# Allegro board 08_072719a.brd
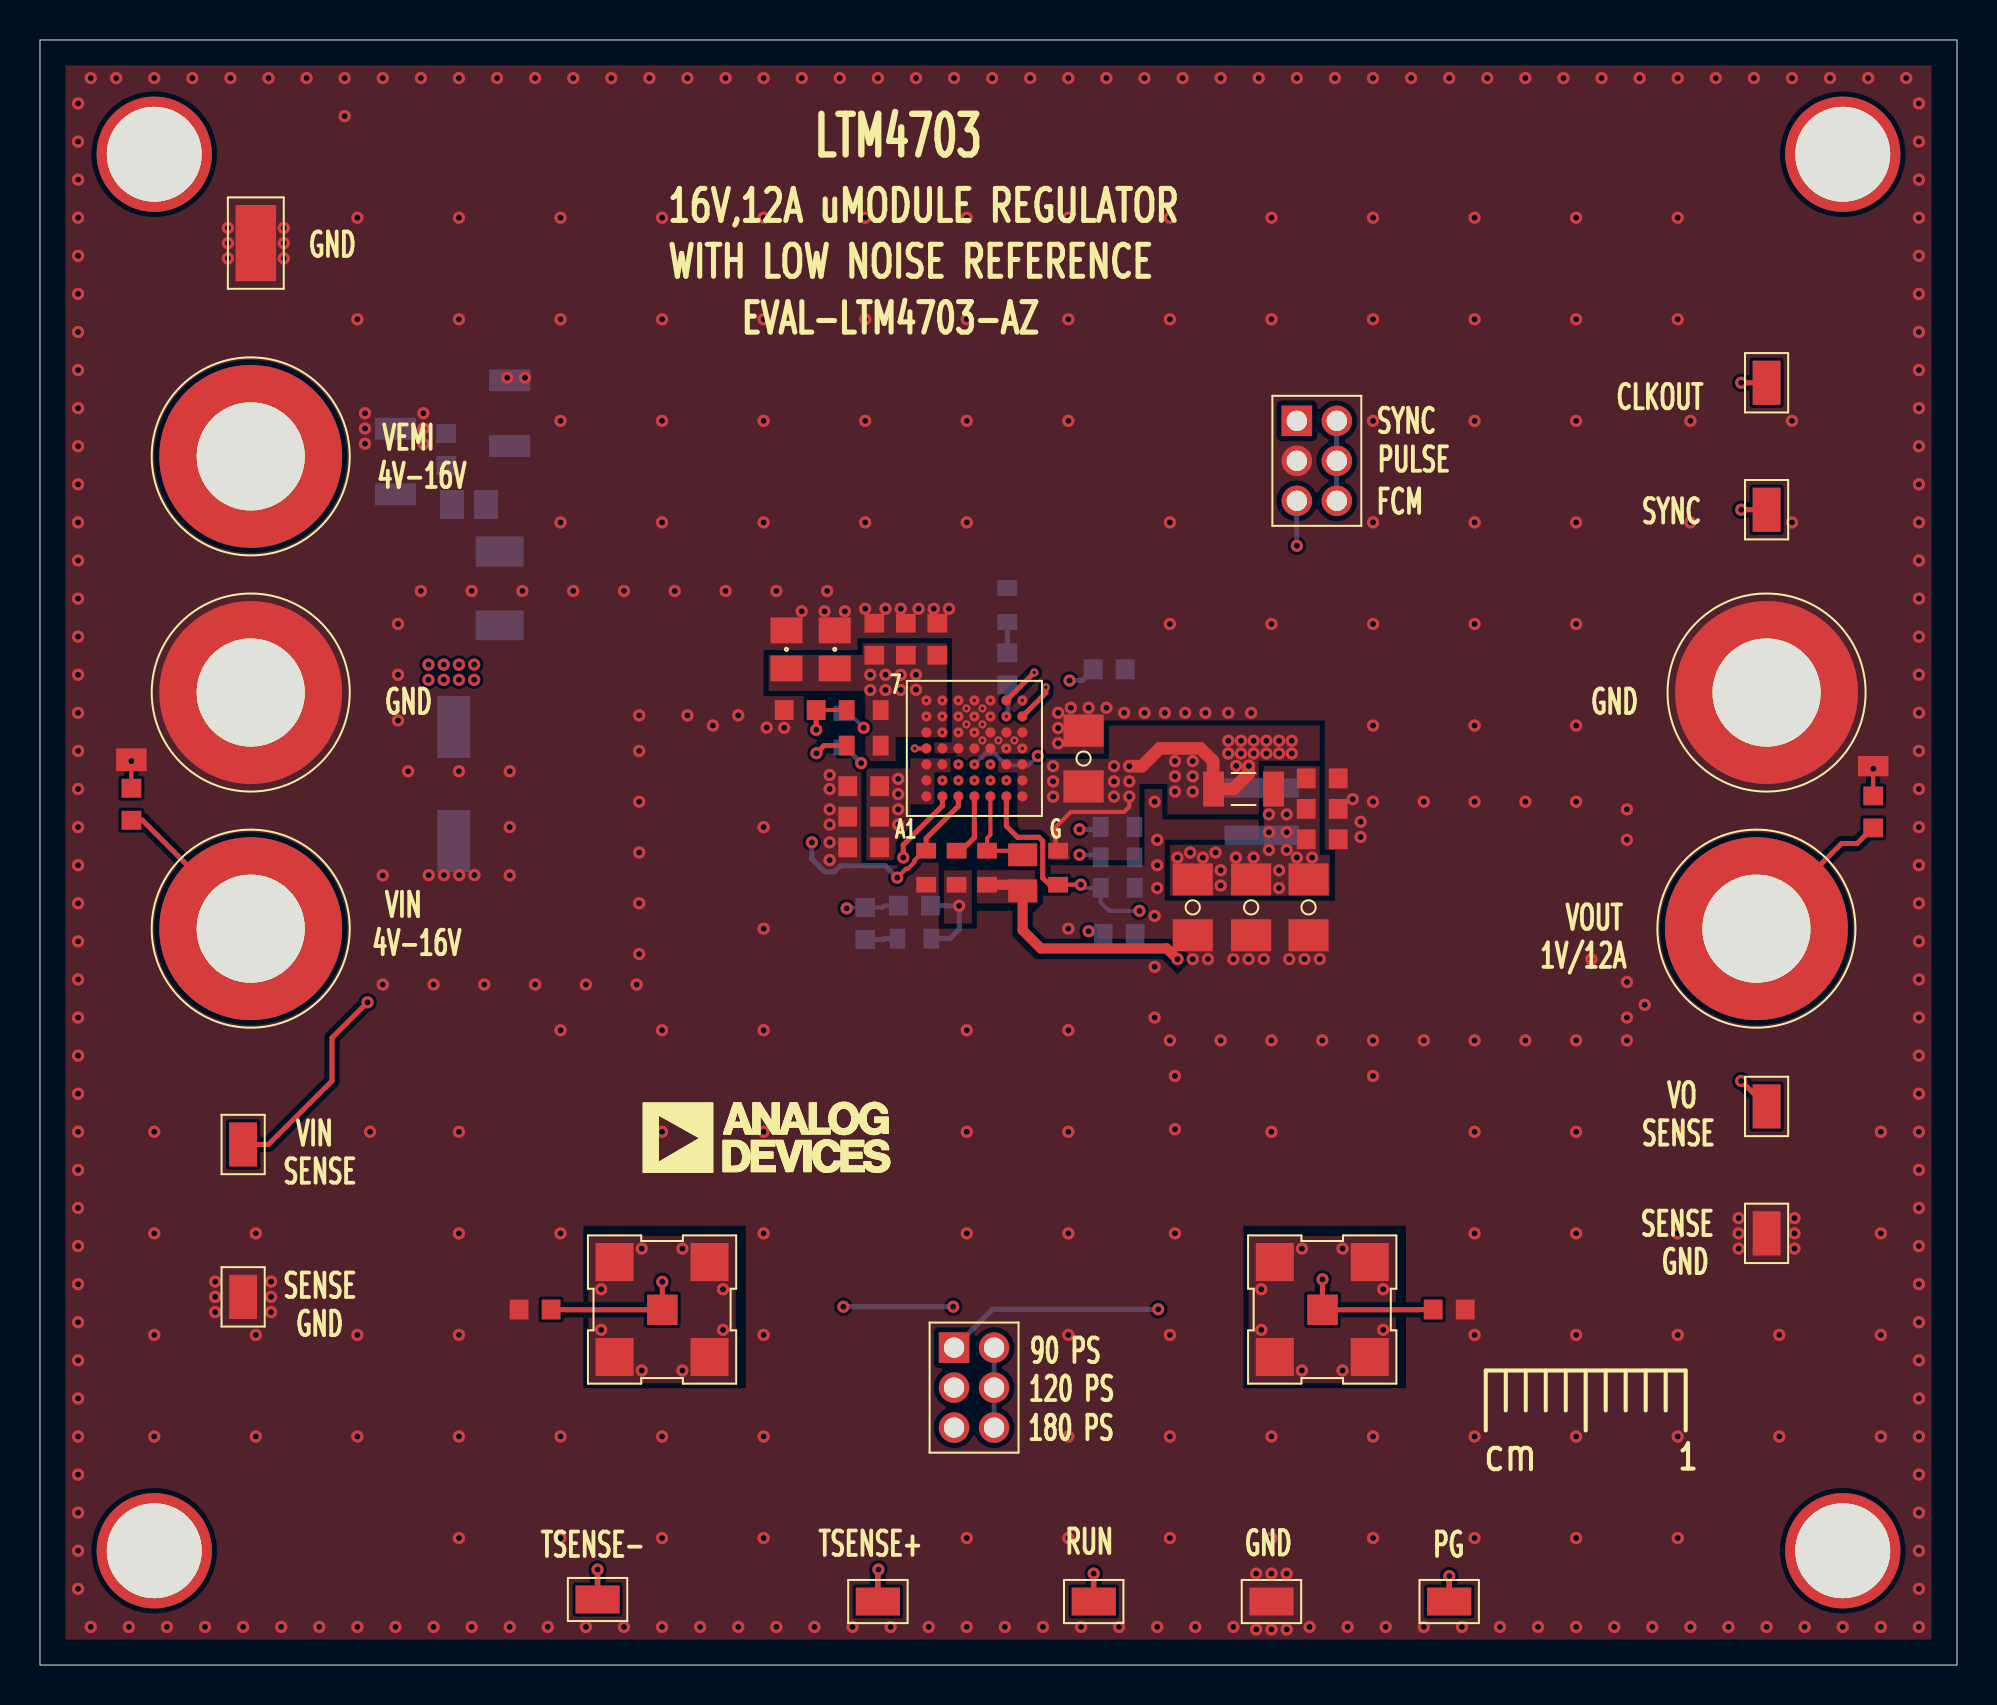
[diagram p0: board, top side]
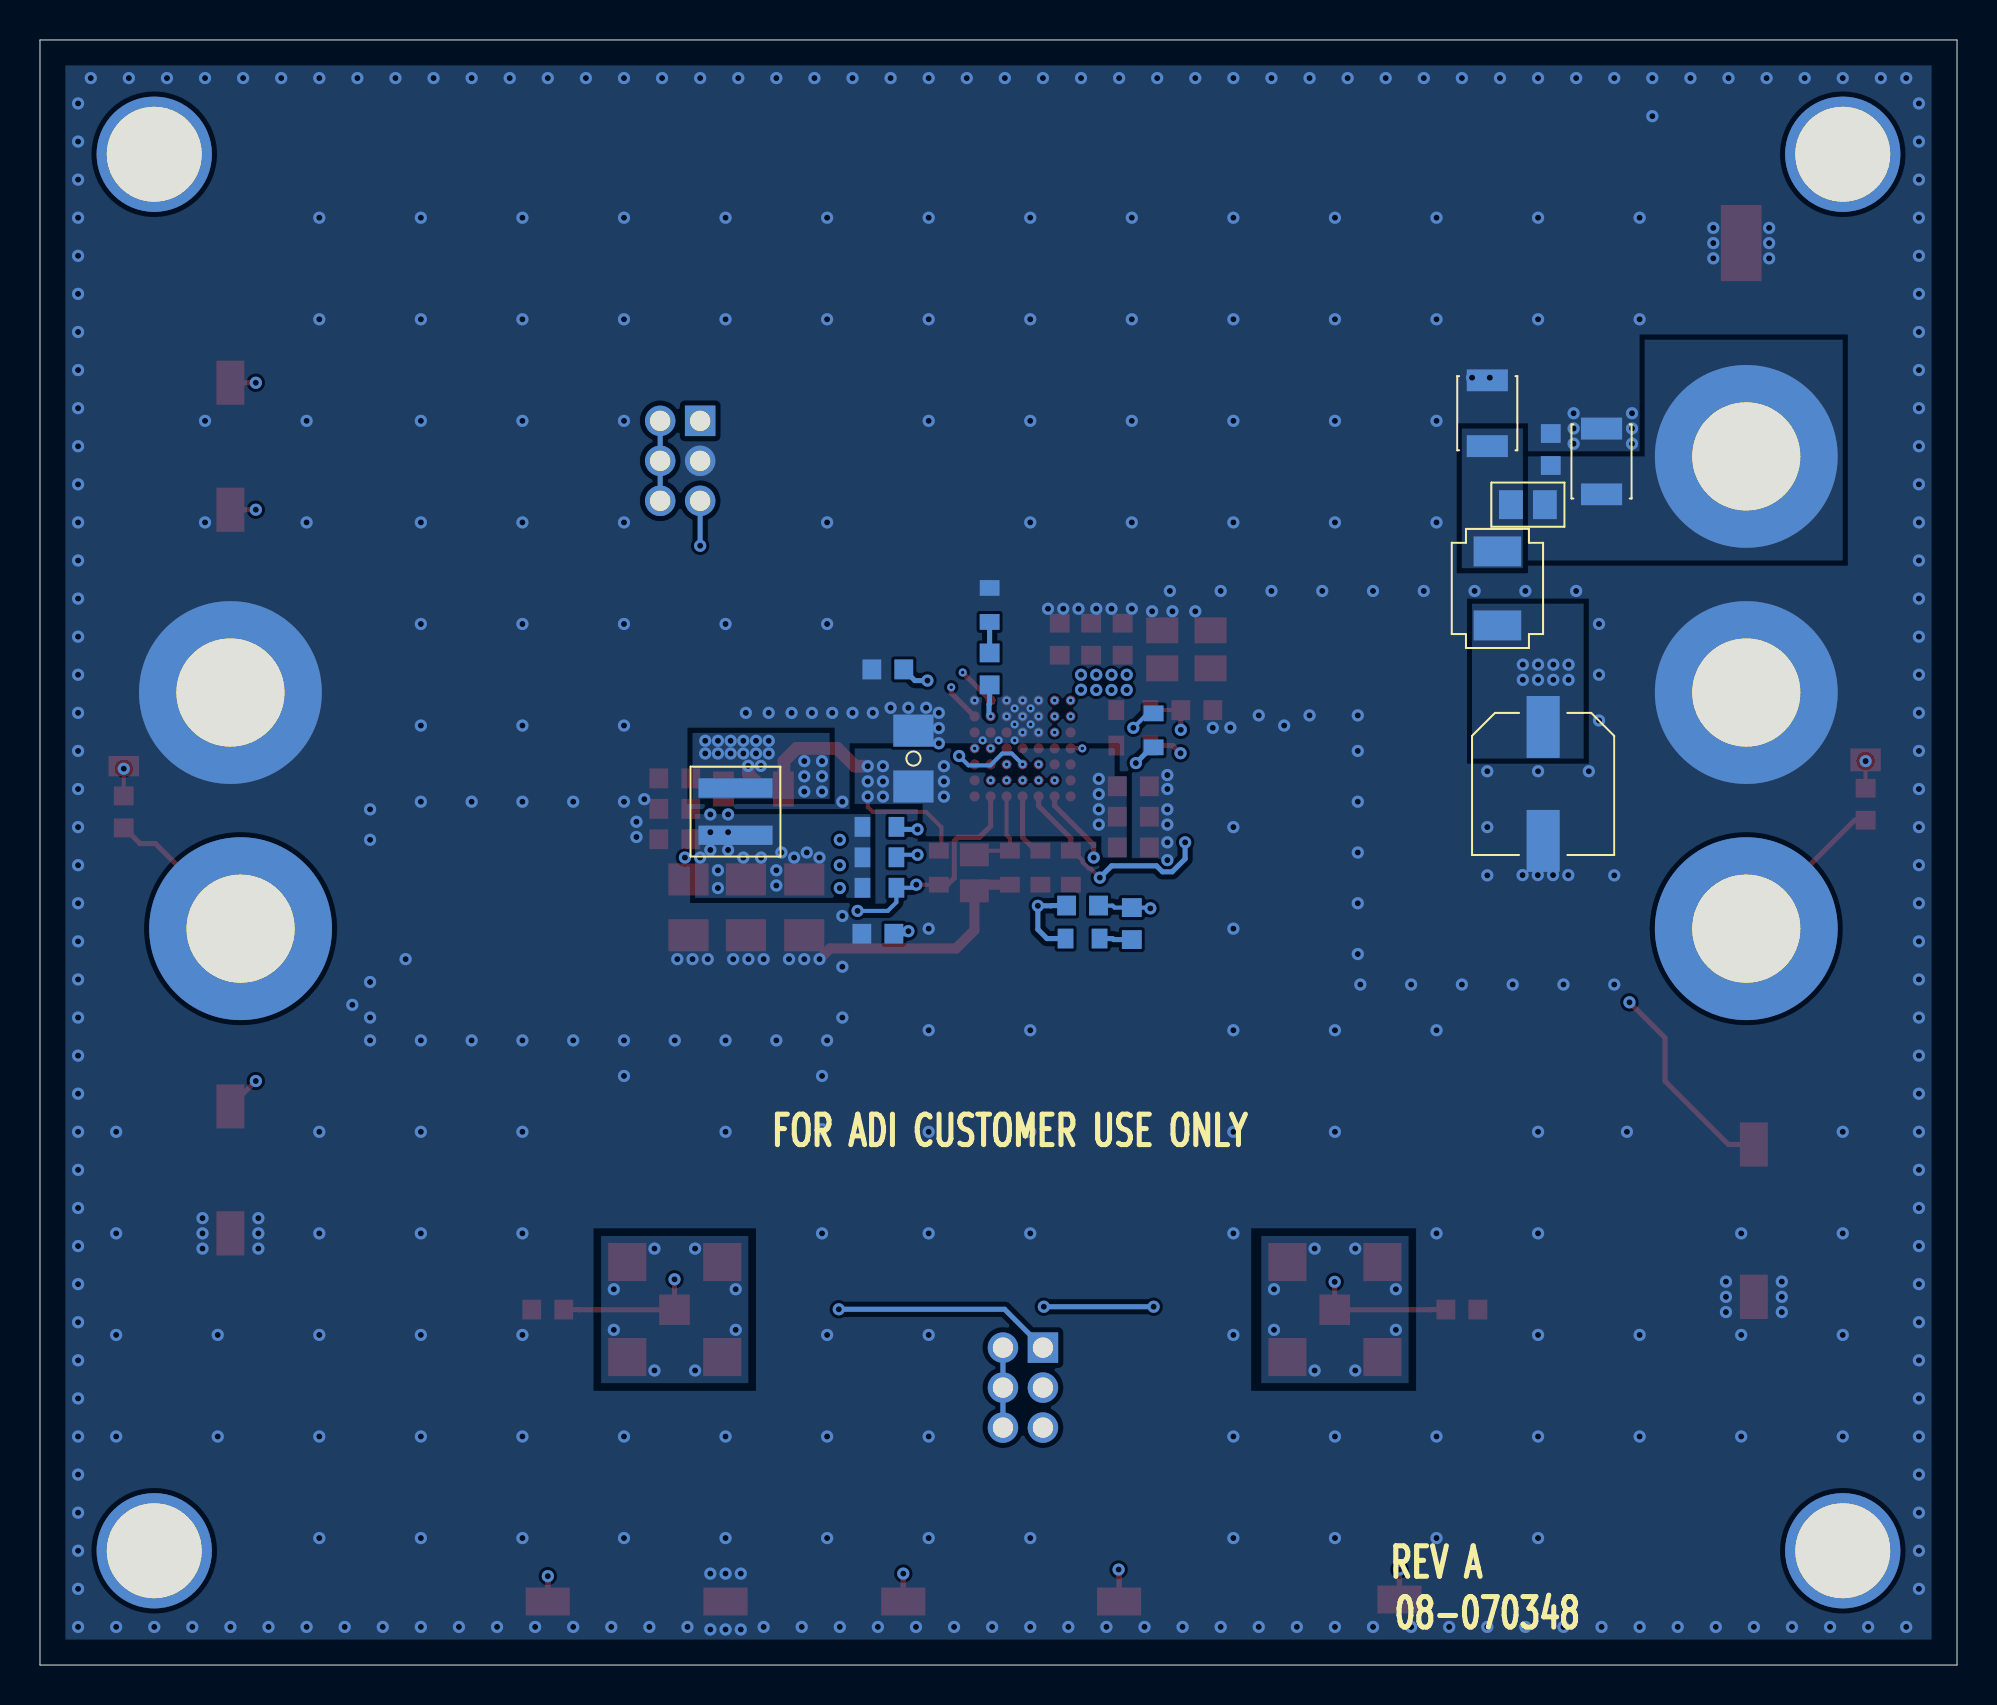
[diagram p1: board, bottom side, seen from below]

Outline 95.89 x 81.28 mm; copper layers: TOP, LAYER2, LAYER3, BOTTOM. Coordinates in mm from the lower left corner of the outline.
Outline path: 0,81.28 0,0 95.89,0 95.89,81.28 0,81.28

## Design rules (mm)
constraint set DEFAULT: min track width 0.203

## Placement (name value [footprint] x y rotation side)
C1  100uF  [CPLSMSQ260H315]  20.7 44.07 270 bottom
C2  22uF  [C0805H60]  39.75 50.8 270 top
C3  2.2uF  [C0603]  4.57 43.05 270 top
C4  2.2uF  [C0603]  43.31 51.31 270 top
C5  2.2uF  [C0603]  41.73 51.31 270 top
C6  100uF  [C1206H71]  52.2 45.34 270 top
C7  TBD0603  [C0603]  53.48 49.8 180 bottom
C8  TBD0603  [C0603]  48.39 49.82 270 bottom
C9  1UF  [C0805H55]  49.15 39.62 90 top
C10  1UF  [C0603]  20.32 60.79 270 bottom
C11  22uF  [C1210H106]  17.78 60.2 270 bottom
C12  22uF  [C1210H106]  23.5 62.61 270 bottom
C13  10uF  [C0603]  41.2 42.43 0 top
C14  10uF  [C0603]  41.2 43.95 0 top
C15  10uF  [C0603]  64.13 42.82 180 top
C16  10uF  [C0603]  91.69 42.67 270 top
C17  100uF  [C1206H71]  63.45 37.9 90 top
C18  0.1uF  [C0603]  38.02 47.76 0 top
C19  100uF  [C1206H71]  52.2 45.34 270 bottom
C20  TBD0603  [C0603]  43.74 37.99 180 bottom
C21  10uF  [C0603]  41.2 40.89 0 top
C22  100uF  [C1206H71]  60.58 37.9 90 top
C23  0.1uF  [C0603]  24.77 17.78 0 top
C24  0.1uF  [C0603]  70.48 17.78 180 top
C25  TBD0603  [C0603]  53.98 36.58 180 bottom
C26  22uF  [C0805H60]  37.34 50.8 270 top
C27  2.2uF  [C0603]  44.88 51.31 270 top
C33  100uF  [C1206H71]  57.66 37.9 90 top
C34  10uF  [C0603]  64.13 44.35 180 top
C35  10uF  [C0603]  64.13 41.3 180 top
C60  0.015UF  [C0603]  41.27 37.08 90 bottom
E1  575-4  [CNBANANAD312LD203]  10.54 36.83 90 top
E2  S2751-46R  [CNHARWINS2751-46R]  61.59 3.17 0 top
E3  575-4  [CNBANANAD312LD203]  85.85 36.83 90 top
E4  S2751-46R  [CNHARWINS2751-46R]  52.7 3.17 0 top
E5  5019  [CNKEY5019]  10.79 71.12 90 top
E6  S2751-46R  [CNHARWINS2751-46R]  10.16 26.03 90 top
E7  S2751-46R  [CNHARWINS2751-46R]  70.48 3.17 0 top
E8  575-4  [CNBANANAD312LD203]  86.36 48.64 90 top
E9  S2751-46R  [CNHARWINS2751-46R]  86.36 64.13 90 top
E10  575-4  [CNBANANAD312LD203]  10.54 48.64 90 top
E11  S2751-46R  [CNHARWINS2751-46R]  86.36 57.79 90 top
E12  S2751-46R  [CNHARWINS2751-46R]  10.16 18.41 90 top
E13  S2751-46R  [CNHARWINS2751-46R]  86.36 21.59 90 top
E14  S2751-46R  [CNHARWINS2751-46R]  41.91 3.17 0 top
E15  S2751-46R  [CNHARWINS2751-46R]  27.89 3.28 0 top
E16  S2751-46R  [CNHARWINS2751-46R]  86.36 27.94 90 top
E17  575-4  [CNBANANAD312LD203]  10.54 60.45 90 top
FB1  30OHM AT 100MEGHZ  [L0805H43]  21.46 58.04 0 bottom
J1  732511350  [CNMOLEX73251135X]  31.12 17.78 0 top
J2  732511350  [CNMOLEX73251135X]  64.13 17.78 0 top
JP1  TMM-103-02-L-D  [CNTHMHDR2X3L236W155H225]  62.87 62.23 270 top
JP2  TMM-103-02-L-D  [CNTHMHDR2X3L236W155H225]  45.72 15.88 270 top
L1  0.1UH  [LSMSQ160H79]  22.99 53.85 270 bottom
L2  0.1UH  [LSMSQ157H122]  61.1 42.68 270 bottom
NOREF  -  []  95.89 81.28 180 top
NOREF#2  -  [unnamed#2]  90.17 75.56 0 top
NOREF#3  -  []  334.01 231.15 0 top
NOREF#4  -  []  0 81.28 270 top
NOREF#5  -  []  -263.02 -230.12 0 top
NOREF#6  -  []  0 81.28 0 top
NOREF#7  -  [unnamed#2]  90.17 5.71 0 top
NOREF#8  -  []  0 0 90 top
NOREF#9  -  [unnamed#2]  5.71 75.56 0 top
NOREF#10  -  []  -218.57 -230.12 0 top
NOREF#11  -  []  95.89 0 90 top
NOREF#12  -  [unnamed#2]  5.71 5.71 0 top
NOREF#13  -  []  148.84 285.24 0 top
NOREF#14  -  []  61.59 257.18 0 top
NOREF#15  -  []  30.15 21.64 0 top
NOREF#16  -  []  72.31 14.73 0 top
NOREF#17  -  []  44.55 29.97 0 top
NOREF#18  -  []  48.77 95.25 0 top
NOREF#19  -  []  89.53 98.42 0 top
NOREF#20  -  []  0 0 0 top
NOREF#21  -  []  -236.86 -233.67 0 top
NOREF#22  -  []  253.49 30.23 180 bottom
R1  49.9K  [R0603]  53.9 40.4 180 bottom
R2  100K  [R0603]  53.9 41.92 0 bottom
R3  10K  [R0603]  47.37 39.88 90 top
R4  1  [R0603]  41.2 47.76 0 top
R5  100K  [R0603]  41.2 45.99 0 top
R6  TBD0603  [R0603]  40.18 46.75 270 bottom
R7  287K  [R0603]  45.85 39.88 90 top
R8  TBD0603  [R0603]  48.39 53.02 270 bottom
R9  TBD0603  [R0603]  44.32 39.88 90 top
R10  0  [R1206]  60.2 43.82 0 top
R11  TBD0603  [R0603]  53.9 38.87 0 bottom
R12  1K  [R0603]  43.74 36.33 180 bottom
R13  0  [R0603]  50.93 39.88 90 top
U1  LTM4703EY#PBF  [BGA49_6_25X6_25_H5_49]  46.74 45.85 0 top

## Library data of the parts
C1 = CAPP: Tolerance: 20; User Part Number: UPN; alternate symbols: (CPLSMSQ260H315); part number: CAPP_SM-100UF,25V,20,E027144,CPLSMSQ260H315; tolerance: 20
C2 C26 = CAP: Tolerance: 20; User Part Number: UPN; alternate symbols: (C0805H60); part number: CAP_SM-22UF,25V,20,E028881,C0805H60; tolerance: 20
C3-C5 C27 = CAP: User Part Number: UPN; Tolerance: 10; alternate symbols: (C0603); part number: CAP_SM-2.2UF,25V,10,E031885,C0603; tolerance: 10
C6 C17 C19 C22 C33 = CAP: Tolerance: 20; User Part Number: UPN; alternate symbols: (C1206H71); part number: CAP_SM-100UF,10V,20,E028061,C1206H71; tolerance: 20
C7 C8 C20 C25 = CAP: User Part Number: UPN; alternate symbols: (C0603); part number: CAP_SM-TBD0603,TBD0603,TBD0603,E000382,C0603
C9 = CAP: User Part Number: UPN; Tolerance: 10; alternate symbols: (C0805H55); part number: CAP_SM-1UF,10V,10,E057045,C0805H55; tolerance: 10
C10 = CAP: User Part Number: UPN; Tolerance: 10; alternate symbols: (C0603); part number: CAP_SM-1UF,25V,10,E044310,C0603; tolerance: 10
C11 C12 = CAP: Tolerance: 10; User Part Number: UPN; alternate symbols: (C1210H106); part number: CAP_SM-22UF,25V,10,E035145,C1210H106; tolerance: 10
C13-C16 C21 C34 C35 = CAP: User Part Number: UPN; Tolerance: 20; alternate symbols: (C0603); part number: CAP_SM-10UF,6.3V,20,E030255,C0603; tolerance: 20
C18 C23 C24 = CAP: User Part Number: UPN; Tolerance: 10; alternate symbols: (C0603); part number: CAP_SM-0.1UF,25V,10,E038719,C0603; tolerance: 10
C60 = CAP: User Part Number: UPN; Tolerance: 1; alternate symbols: (C0603); part number: CAP_SM-0.015UF,25V,1,E056602,C0603; tolerance: 1
E1 E3 E8 E10 E17 = CNTP1P: Tolerance: N/A; User Part Number: UPN; alternate symbols: (CNBANANAD312LD203); part number: CNTP1P_TH-575-4,E012555,CNBANANAD312LD203; tolerance: N/A
E2 E4 E6 E7 E9 E11-E16 = CNTP1P: User Part Number: UPN; Tolerance: N/A; alternate symbols: (CNHARWINS2751-46R); part number: CNTP1P_SM-S2751-46R,E046173,CNHARWINS2751-46R; tolerance: N/A
E5 = CNTP1P: User Part Number: UPN; Tolerance: N/A; alternate symbols: (CNKEY5019); part number: CNTP1P_SM-5019,E021431,CNKEY5019; tolerance: N/A
FB1 = FERRITE: User Part Number: UPN; Tolerance: 25; alternate symbols: (L0805H43); part number: FERRITE_SM-30OHM AT 100MEGHZ,25,E056279,L0805H43; tolerance: 25
J1 J2 = CNBNC5P: Tolerance: N/A; User Part Number: UPN; alternate symbols: (CNMOLEX73251135X); part number: CNBNC5P_SM-732511350,E046175,CNMOLEX73251135X; tolerance: N/A
JP1 JP2 = CN6P_JMPRSHRT: User Part Number: UPN; Tolerance: N/A; alternate symbols: (CNTHMHDR2X3L236W155H225); part number: CN6P_JMPRSHRT_TH-TMM-103-02-L-D,E043044,CNTHMHDR2X3L236W155H225; tolerance: N/A
L1 = IND: User Part Number: UPN; Tolerance: 30; alternate symbols: (LSMSQ160H79); part number: IND_SM-0.1UH,30,E046378,LSMSQ160H79; tolerance: 30
L2 = IND: User Part Number: UPN; Tolerance: 20; alternate symbols: (LSMSQ157H122); part number: IND_SM-0.1UH,20,E046177,LSMSQ157H122; tolerance: 20
R1 = RES: User Part Number: UPN; Tolerance: 1; alternate symbols: (R0603); part number: RES_SM-49.9K,E015342,1/10W,1,R0603; tolerance: 1
R2 R5 = RES: User Part Number: UPN; Tolerance: 1; alternate symbols: (R0603); part number: RES_SM-100K,E010279,1/10W,1,R0603; tolerance: 1
R3 = RES: User Part Number: UPN; Tolerance: 1; alternate symbols: (R0603); part number: RES_SM-10K,E003671,1/10W,1,R0603; tolerance: 1
R4 = RES: User Part Number: UPN; alternate symbols: (R0603); part number: RES_SM-1,E015181,1/10W,1,R0603
R6 R8 R9 R11 = RES: User Part Number: UPN; alternate symbols: (R0603); part number: RES_SM-TBD0603,E004050,TBD0603,TBD0603,R0603
R7 = RES: User Part Number: UPN; Tolerance: 1; alternate symbols: (R0603); part number: RES_SM-287K,E026586,1/10W,1,R0603; tolerance: 1
R10 = RES: User Part Number: UPN; Tolerance: 1; alternate symbols: (R1206); part number: RES_SM-0,E031388,1/4W,1,R1206; tolerance: 1
R12 = RES: User Part Number: UPN; Tolerance: 1; alternate symbols: (R0603); part number: RES_SM-1K,E003678,1/10W,1,R0603; tolerance: 1
R13 = RES: User Part Number: UPN; Tolerance: JUMPER; alternate symbols: (R0603); part number: RES_SM-0,E007502,1/10W,JUMPER,R0603; tolerance: JUMPER
U1 = ADLTM4703_V2: Tolerance: N/A; User Part Number: UPN; alternate symbols: (BGA49_6_25X6_25_H5_49); part number: ADLTM4703_V2_SM-LTM4703EY#PBF,E058729,BGA49_6_25X6_25_H5_49; tolerance: N/A

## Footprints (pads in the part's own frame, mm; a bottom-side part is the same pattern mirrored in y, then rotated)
BGA49_6_25X6_25_H5_49
  round 0.508 smd: A1(-2.4,-2.4) A2(-2.4,-1.6) A3(-2.4,-0.8) A4(-2.4,0) A5(-2.4,0.8) A6(-2.4,1.6) A7(-2.4,2.4) B1(-1.6,-2.4) B2(-1.6,-1.6) B3(-1.6,-0.8) B4(-1.6,0) B5(-1.6,0.8) B6(-1.6,1.6) B7(-1.6,2.4) C1(-0.8,-2.4) C2(-0.8,-1.6) C3(-0.8,-0.8) C4(-0.8,0) C5(-0.8,0.8) C6(-0.8,1.6) C7(-0.8,2.4) D1(0,-2.4) D2(0,-1.6) D3(0,-0.8) D4(0,0) D5(0,0.8) D6(0,1.6) D7(0,2.4) E1(0.8,-2.4) E2(0.8,-1.6) E3(0.8,-0.8) E4(0.8,0) E5(0.8,0.8) E6(0.8,1.6) E7(0.8,2.4) F1(1.6,-2.4) F2(1.6,-1.6) F3(1.6,-0.8) F4(1.6,0) F5(1.6,0.8) F6(1.6,1.6) F7(1.6,2.4) G1(2.4,-2.4) G2(2.4,-1.6) G3(2.4,-0.8) G4(2.4,0) G5(2.4,0.8) G6(2.4,1.6) G7(2.4,2.4)
C0603
  rect 0.94x0.991 smd: 1(-0.8,0) 2(0.8,0)
C0805H55
  rect 1.143x1.448 smd: 1(-0.9,0) 2(0.9,0)
C0805H60
  rect 1.295x1.6 smd: 1(-0.953,0) 2(0.953,0)
C1206H71
  rect 1.6x2.007 smd: 1(-1.397,0) 2(1.397,0)
C1210H106
  rect 1.092x2.057 smd: 1(-1.646,0) 2(1.646,0)
CNBANANAD312LD203
  round 9.144 hole 5.41: 1(0,0)
CNHARWINS2751-46R
  rect 2.21x1.397 smd: 1(0,0)
CNKEY5019
  rect 3.81x2.032 smd: 1(0,0)
CNMOLEX73251135X
  rect 1.524x1.524 smd: 1(0.013,-0.013)
  rect 1.905x1.905 smd: 2(-2.375,-2.375) 3(2.375,-2.375) 4(2.375,2.375) 5(-2.375,2.375)
CNTHMHDR2X3L236W155H225
  rect 1.524x1.524 hole 1.016: 1(0,0)
  round 1.524 hole 1.016: 2(0,2) 3(2,0) 4(2,2) 5(4,0) 6(4,2)
CPLSMSQ260H315
  rect 3.099x1.651 smd: N(2.85,0) P(-2.85,0)
L0805H43
  rect 1.194x1.448 smd: 1(-0.85,0) 2(0.85,0)
LSMSQ157H122
  rect 0.965x3.708 smd: 1(-1.181,0) 2(1.181,0)
LSMSQ160H79
  rect 1.499x2.388 smd: 1(-1.849,0) 2(1.849,0)
R0603
  rect 0.787x0.991 smd: 1(-0.85,0) 2(0.85,0)
R1206
  rect 1.041x1.753 smd: 1(-1.5,0) 2(1.5,0)
unnamed#2
  round 5.766 hole 4.75 unplated: (0,0)

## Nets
DGND_A: C3.1 J1.2 J1.3 J1.4 J1.5(SH4)
DGND_B: C16.1 J2.2 J2.3 J2.4 J2.5(SH4)
GND_SIGNAL: C20.1 JP2.5 R7.1 R12.1 U1.D2
VIN: C1.P C2.2(N2) C3.2(N2) C4.2(N2) C5.2(N2) C23.2(N2) C26.2(N2) C27.2(N2) E1.1(N1) E6.1(N1) J1.1 L1.2(N2) R4.2(N2) R5.2(N2) U1.A5 U1.A6 U1.A7 U1.B5 U1.B6 U1.B7
CLKOUT: E9.1(N1) U1.F7
COMPA: C20.2(N2) C60.2(N2) R6.2(N2) U1.C2
COMPB: R6.1 U1.C3
DUTVOUT: C6.2(N2) C13.2(N2) C14.2(N2) C19.2(N2) C21.2(N2) L2.1 R10.1 R13.2(N2) U1.A1 U1.A2 U1.A3 U1.B3 U1.F3 U1.G1 U1.G2 U1.G3(VOUT_8)
GROUND: C1.N(N2) C2.1 C4.1 C5.1 C6.1 C7.1 C9.1 C10.1 C11.1 C12.1 C13.1 C14.1 C15.1 C17.1 C18.1 C19.1 C21.1 C22.1 C23.1 C24.1 C25.1 C26.1 C27.1 C33.1 C34.1 C35.1 E2.1(N1) E5.1(N1) E8.1(N1) E10.1(N1) E12.1(N1) E13.1(N1) JP1.3 R3.1 R8.1 R9.1 U1.B4 U1.C4 U1.C5 U1.C6 U1.C7 U1.D4 U1.D5 U1.D6 U1.D7 U1.E4 U1.E5 U1.E6 U1.E7 U1.F4 U1.F5 U1.G4 U1.G5 U1.G7
INTVCC: C7.2(N2) JP1.5 JP2.1 U1.D3
PG: E7.1(N1) R2.1 U1.F2
PGSET: C25.2(N2) R1.2(N2) U1.E2
PHMODE: JP2.2 JP2.4 JP2.6(S6) U1.E3
RT: R7.2(N2) U1.D1
RUN: E4.1(N1) R5.1 R9.2(N2) U1.C1
SET: C9.2(N2) R3.2(N2) U1.E1
SVN: C18.2(N2) R4.1 U1.A4
SW: C8.2(N2) U1.F6
SYNC: JP1.2 JP1.4 JP1.6(S6) U1.G6
TSENSE+: E14.1(N1) U1.B1
TSENSE-: E15.1(N1) U1.B2
UNNAMED_6_CAP_I11_N1: C60.1 R12.2(N2)
UNNAMED_6_CAP_I100_N2: C12.2(N2) FB1.2(N2) L1.1
UNNAMED_6_CAP_I138_N1: C8.1 R8.2(N2)
UNNAMED_6_CN6PJMPRSHRT_I48_S1: E11.1(N1) JP1.1
VEMI: C10.2(N2) C11.2(N2) E17.1(N1) FB1.1
VOSNS: E16.1(N1) R11.1 R13.1 U1.F1
VOUT: C15.2(N2) C16.2(N2) C17.2(N2) C22.2(N2) C24.2(N2) C33.2(N2) C34.2(N2) C35.2(N2) E3.1(N1) J2.1 L2.2(N2) R1.1 R2.2(N2) R10.2(N2) R11.2(N2)

Pads without a net: JP2 3

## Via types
v1: diameter 0.61, hole 0.305, TOP to BOTTOM, 565 vias
v2: diameter 0.406, hole 0.178, TOP to BOTTOM, 35 vias

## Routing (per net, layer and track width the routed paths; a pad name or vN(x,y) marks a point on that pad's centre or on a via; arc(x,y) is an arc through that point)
DGND_A: length 46.6
  TOP w0.203: v1(4.57,45.21) C3.1
  LAYER3 w0.254: v1(4.57,45.21) 4.57,44.53 4.45,44.4 4.45,33.38 7.62,30.2 25.04,30.2 30.1,25.15 v1(30.1,20.83)
  vias: v1(28.07,18.8) v1(28.07,16.76) v1(30.1,14.73) v1(32.13,20.83) v1(32.13,14.73) v1(34.16,18.8) v1(34.16,16.76)
DGND_B: length 47.6
  TOP w0.203: v1(91.69,44.83) C16.1
  LAYER3 w0.203: v1(91.69,44.83) 91.69,31.24 88.01,27.56 68.83,27.56 65.15,23.88 v1(65.15,20.83)
  vias: v1(61.09,18.8) v1(61.09,16.76) v1(63.12,20.83) v1(63.12,14.73) v1(65.15,14.73) v1(67.18,18.8) v1(67.18,16.76)
GND_SIGNAL: length 37.1
  LAYER3 w0.254: JP2.5 44.21,13.39 44.21,36.21 v1(45.97,37.97)
  LAYER3 w0.381: 46.74,43.54 v2(46.74,44.25)
  LAYER3 w0.508: 46.74,43.54 45.87,42.67 45.87,39.19
  BOTTOM w0.254: R12.1 45.52,36.33 45.97,36.79 v1(45.97,37.97) 45.31,37.97 45.3,37.99 C20.1
VIN: length 100.5
  TOP w0.254: C3.2 5.12,42.25 E1.1 ; v1(31.13,19.16) J1.1 26.31,17.77 26.3,17.78 C23.2 ; v1(16.38,33.15) 14.61,31.37 14.61,29.21 11.43,26.03 E6.1
  LAYER3 w0.203: 36.21,47.79 43.6,47.79 43.82,48.01 v1(43.82,48.78)
  LAYER3 w0.254: E1.1 9.91,36.2 9.91,31.75 10.92,30.73 25.27,30.73 31.13,24.88 v1(31.13,19.16) ; v1(16.38,33.15) 30.73,33.15 33.91,36.32 33.91,45.49 36.21,47.79
  vias: v1(19.43,50.04) v1(19.43,49.28) v1(20.19,50.04) v1(20.19,49.28) v1(20.95,50.04) v1(20.95,49.28) v1(21.72,50.04) v1(21.72,49.28) v1(41.53,49.53) v1(41.53,48.77) v1(42.29,49.53) v1(42.29,48.77) v1(43.05,49.53) v1(43.05,48.77) v1(43.81,49.53) v2(44.34,48.25) v2(44.34,47.45) v2(45.14,48.25) v2(45.14,47.45) v2(45.14,46.65)
CLKOUT: length 49.4
  TOP w0.254: E9.1 v1(85.09,64.13) ; U1.F7 v2(49.73,49.64)
  LAYER3 w0.254: v1(85.09,64.13) 82.92,66.31 61.23,66.31 49.73,54.81 v2(49.73,49.64)
COMPA: length 16.7
  LAYER3 w0.203: v2(45.94,44.25) 45.22,44.96 41.89,44.96 41.73,45.11 v1(41.07,45.11)
  LAYER3 w0.254: v1(41.07,45.11) 41.07,40.65 40.35,39.93 v1(40.35,37.85)
  BOTTOM w0.203: v1(40.35,37.85) 40.39,37.88 C60.2 42.14,37.88 42.24,37.99 C20.2
  BOTTOM w0.254: v1(41.07,45.11) 40.28,45.9 R6.2
COMPB: length 6.8
  LAYER3 w0.254: v2(45.94,45.05) 45.52,45.46 44.99,45.46 43.57,46.88 v1(41.2,46.88)
  BOTTOM w0.203: R6.1 40.48,47.6 v1(41.2,46.88)
DUTVOUT: length 14.5
  TOP w0.203: v1(54.48,43.43) 54.48,42.93 54.23,42.67 51.56,42.67 50.8,41.91 50.8,40.85 R13.2
  TOP w0.635: v1(60.46,44.97) 60.45,44.96 60.45,44.58 59.69,43.82 R10.1 58.67,43.84 58.67,45.21 58.04,45.85 56.01,45.85 55.12,44.96 v1(54.48,44.96)
  vias: v1(42.93,44.32) v1(42.93,43.56) v1(42.93,42.8) v1(42.93,42.04) v1(50.67,44.96) v1(50.67,44.2) v1(50.67,43.43) v1(53.72,44.96) v1(53.72,44.2) v1(53.72,43.43) v1(54.48,44.2) v1(56.77,45.21) v1(56.77,44.45) v1(56.77,43.69) v1(57.66,45.21) v1(57.66,44.45) v1(57.66,43.69) v1(59.44,46.23) v1(59.44,45.59) v1(59.83,44.97) v1(60.07,46.23) v1(60.07,45.59) v1(60.71,46.23) v1(60.71,45.59) v1(61.34,46.23) v1(61.34,45.59) v1(61.98,46.23) v1(61.98,45.59) v1(62.61,46.23) v1(62.61,45.59)
GROUND: length 12.4
  TOP w0.508: v1(56.9,35.31) 56.36,35.84 50.06,35.84 49.15,36.75 C9.1 48.84,39.03 R3.1
  LAYER2 w0.203: 53.31,48.79 53.33,48.77 ; 54.69,38.66 54.79,38.56
  vias: v1(1.9,78.1) v1(1.9,76.2) v1(1.9,74.29) v1(1.9,72.39) v1(1.9,70.48) v1(1.9,68.58) v1(1.9,66.67) v1(1.9,64.77) v1(1.9,62.87) v1(1.9,60.96) v1(1.9,59.05) v1(1.9,57.15) v1(1.9,55.25) v1(1.9,53.34) v1(1.9,51.44) v1(1.9,49.53) v1(1.9,47.62) v1(1.9,45.72) v1(1.9,43.82) v1(1.9,41.91) v1(1.9,40.01) v1(1.9,38.1) v1(1.9,36.2) v1(1.9,34.29) v1(1.9,32.38) v1(1.9,30.48) v1(1.9,28.58) v1(1.9,26.67) v1(1.9,24.77) v1(1.9,22.86) v1(1.9,20.95) v1(1.9,19.05) v1(1.9,17.14) v1(1.9,15.24) v1(1.9,13.34) v1(1.9,11.43) v1(1.9,9.52) v1(1.9,7.62) v1(1.9,5.71) v1(1.9,3.81) v1(2.54,79.38) v1(2.54,1.9) v1(3.81,79.38) v1(4.45,1.9) v1(5.71,79.38) v1(5.71,26.67) v1(5.71,21.59) v1(5.71,16.51) v1(5.71,11.43) v1(6.35,1.9) v1(7.62,79.38) v1(8.25,1.9) v1(8.76,19.18) v1(8.76,18.41) v1(8.76,17.65) v1(9.4,71.88) v1(9.4,71.12) v1(9.4,70.36) v1(9.53,79.38) v1(10.16,1.9) v1(10.79,21.59) v1(10.79,16.51) v1(10.79,11.43) v1(11.43,79.38) v1(11.56,19.18) v1(11.56,18.41) v1(11.56,17.65) v1(12.06,1.9) v1(12.19,71.88) v1(12.19,71.12) v1(12.19,70.36) v1(13.34,79.38) v1(13.97,1.9) v1(15.24,79.38) v1(15.24,77.47) v1(15.88,72.39) v1(15.88,67.31) v1(15.88,16.51) v1(15.88,11.43) v1(15.88,1.9) v1(16.26,62.61) v1(16.26,61.85) v1(16.26,61.09) v1(16.51,26.67) v1(17.14,79.38) v1(17.14,39.5) v1(17.14,34.04) v1(17.78,1.9) v1(17.91,52.07) v1(17.91,49.53) v1(17.91,47.24) v1(18.41,44.7) v1(19.05,79.38) v1(19.05,53.72) v1(19.18,62.61) v1(19.18,61.85) v1(19.18,61.09) v1(19.44,39.51) v1(19.68,34.04) v1(19.68,1.9) v1(20.21,39.51) v1(20.95,79.38) v1(20.95,72.39) v1(20.95,67.31) v1(20.95,44.7) v1(20.97,39.51) v1(20.95,26.67) v1(20.95,21.59) v1(20.95,16.51) v1(20.95,11.43) v1(20.95,6.35) v1(21.59,53.72) v1(21.59,1.9) v1(21.73,39.51) v1(22.23,34.04) v1(22.86,79.38) v1(23.37,64.39) v1(23.5,44.7) v1(23.5,41.91) v1(23.5,39.5) v1(23.5,1.9) v1(24.13,53.72) v1(24.26,64.39) v1(24.77,79.38) v1(24.77,34.04) v1(25.4,1.9) v1(26.04,72.39) v1(26.04,67.31) v1(26.04,62.23) v1(26.04,57.15) v1(26.04,31.75) v1(26.04,21.59) v1(26.04,11.43) v1(26.04,6.35) v1(26.67,79.38) v1(26.67,53.72) v1(27.3,34.04) v1(27.3,1.9) v1(28.57,79.38) v1(29.21,53.72) v1(29.21,1.9) v1(29.84,34.04) v1(29.97,47.5) v1(29.97,45.72) v1(29.97,43.18) v1(29.97,40.64) v1(29.97,38.1) v1(29.97,35.56) v1(30.48,79.38) v1(31.12,72.39) v1(31.12,67.31) v1(31.12,62.23) v1(31.12,57.15) v1(31.12,31.75) v1(31.12,26.67) v1(31.12,11.43) v1(31.12,6.35) v1(31.12,1.9) v1(31.75,53.72) v1(32.39,79.38) v1(32.39,47.5) v1(33.02,1.9) v1(33.66,46.99) v1(34.29,79.38) v1(34.29,53.72) v1(34.92,47.5) v1(34.92,1.9) v1(36.2,79.38) v1(36.2,72.39) v1(36.2,67.31) v1(36.2,62.23) v1(36.2,57.15) v1(36.2,41.91) v1(36.2,36.83) v1(36.2,31.75) v1(36.2,26.67) v1(36.2,21.59) v1(36.2,16.51) v1(36.2,11.43) v1(36.2,6.35) v1(36.35,46.89) v1(36.83,53.72) v1(36.83,1.9) v1(37.22,46.88) v1(38.1,79.38) v1(38.1,52.7) v1(38.73,1.9) v1(39.24,52.7) v1(39.37,53.72) v1(39.5,44.51) v1(39.5,43.82) v1(39.5,42.8) v1(39.5,42.04) v1(39.5,41.15) v1(39.5,40.26) v1(40,79.38) v1(40.26,52.7) v1(40.64,1.9) v1(41.27,72.39) v1(41.27,67.31) v1(41.27,62.23) v1(41.27,57.15) v1(41.27,52.83) v1(41.91,79.38) v1(42.29,52.83) v1(42.55,1.9) v1(43.05,52.83) v1(43.81,79.38) v1(43.94,52.83) v1(44.45,1.9) v1(44.7,52.83) v1(45.47,52.83) v1(45.72,79.38) v1(46.36,72.39) v1(46.36,67.31) v1(46.36,62.23) v1(46.36,57.15) v1(46.36,31.75) v1(46.36,26.67) v1(46.36,21.59) v1(46.36,6.35) v1(46.36,1.9) v1(47.62,79.38) v1(48.26,1.9) v1(49.53,79.38) v1(50.16,1.9) v1(50.93,47.62) v1(50.93,46.86) v1(50.93,46.1) v1(51.44,79.38) v1(51.44,72.39) v1(51.44,67.31) v1(51.44,62.23) v1(51.44,36.83) v1(51.44,31.75) v1(51.44,26.67) v1(51.44,21.59) v1(51.44,16.51) v1(51.44,11.43) v1(51.44,6.35) v1(51.56,47.88) v1(52.07,1.9) v1(52.45,47.88) v1(53.34,79.38) v1(53.34,47.88) v1(53.98,1.9) v1(54.23,47.62) v1(55.24,79.38) v1(55.24,47.62) v1(55.75,43.18) v1(55.75,37.46) v1(55.75,34.92) v1(55.75,32.38) v1(55.88,41.27) v1(55.88,40.01) v1(55.88,38.86) v1(55.88,1.9) v1(56.26,47.62) v1(56.52,72.39) v1(56.52,67.31) v1(56.52,57.15) v1(56.52,52.07) v1(56.52,31.24) v1(56.52,16.51) v1(56.52,11.43) v1(56.52,6.35) v1(56.77,29.46) v1(56.77,26.8) v1(56.77,21.59) v1(57.15,79.38) v1(57.28,47.62) v1(57.66,35.31) v1(57.78,1.9) v1(58.29,47.62) v1(58.42,35.31) v1(59.05,79.38) v1(59.05,31.24) v1(59.44,47.62) v1(59.69,35.31) v1(59.69,1.9) v1(60.45,35.31) v1(60.58,47.62) v1(60.83,4.57) v1(60.83,1.78) v1(60.96,79.38) v1(61.21,35.31) v1(61.59,72.39) v1(61.59,67.31) v1(61.59,52.07) v1(61.59,31.24) v1(61.59,26.67) v1(61.59,11.43) v1(61.59,6.35) v1(61.59,4.57) v1(61.59,1.78) v1(62.36,4.57) v1(62.36,1.78) v1(62.48,35.31) v1(62.87,79.38) v1(63.25,35.31) v1(63.5,1.9) v1(64.01,35.31) v1(64.13,31.24) v1(64.77,79.38) v1(65.41,1.9) v1(65.66,43.31) v1(66.05,42.18) v1(66.05,41.41) v1(66.67,79.38) v1(66.67,72.39) v1(66.67,67.31) v1(66.67,62.23) v1(66.67,57.15) v1(66.67,52.07) v1(66.67,46.99) v1(66.67,43.18) v1(66.67,31.24) v1(66.67,29.46) v1(66.67,11.43) v1(66.67,6.35) v1(67.31,1.9) v1(68.58,79.38) v1(69.22,43.18) v1(69.22,31.24) v1(69.22,1.9) v1(70.48,79.38) v1(71.12,1.9) v1(71.75,72.39) v1(71.75,67.31) v1(71.75,62.23) v1(71.75,57.15) v1(71.75,52.07) v1(71.75,46.99) v1(71.75,43.18) v1(71.75,31.24) v1(71.75,26.67) v1(71.75,21.59) v1(71.75,16.51) v1(71.75,11.43) v1(71.75,6.35) v1(72.39,79.38) v1(73.03,1.9) v1(74.3,79.38) v1(74.3,43.18) v1(74.3,31.24) v1(74.93,1.9) v1(76.2,79.38) v1(76.84,72.39) v1(76.84,67.31) v1(76.84,62.23) v1(76.84,57.15) v1(76.84,52.07) v1(76.84,46.99) v1(76.84,43.18) v1(76.84,31.24) v1(76.84,26.67) v1(76.84,21.59) v1(76.84,16.51) v1(76.84,11.43) v1(76.84,6.35) v1(76.84,1.9) v1(77.6,35.31) v1(78.1,79.38) v1(78.74,1.9) v1(79.38,42.8) v1(79.38,41.27) v1(79.38,34.16) v1(79.38,32.38) v1(79.38,31.24) v1(80.01,79.38) v1(80.26,33.02) v1(80.64,1.9) v1(81.92,79.38) v1(81.92,72.39) v1(81.92,67.31) v1(81.92,26.67) v1(81.92,21.59) v1(81.92,16.51) v1(81.92,11.43) v1(81.92,6.35) v1(82.55,62.23) v1(82.55,57.15) v1(82.55,1.9) v1(83.82,79.38) v1(84.45,1.9) v1(84.96,22.35) v1(84.96,21.59) v1(84.96,20.83) v1(85.72,79.38) v1(86.36,1.9) v1(87,16.51) v1(87,11.43) v1(87.63,79.38) v1(87.63,62.23) v1(87.63,57.15) v1(87.76,22.35) v1(87.76,21.59) v1(87.76,20.83) v1(88.27,1.9) v1(89.53,79.38) v1(90.17,1.9) v1(91.44,79.38) v1(92.08,26.67) v1(92.08,21.59) v1(92.08,16.51) v1(92.08,11.43) v1(92.08,1.9) v1(93.34,79.38) v1(93.98,78.1) v1(93.98,76.2) v1(93.98,74.29) v1(93.98,72.39) v1(93.98,70.48) v1(93.98,68.58) v1(93.98,66.67) v1(93.98,64.77) v1(93.98,62.87) v1(93.98,60.96) v1(93.98,59.05) v1(93.98,57.15) v1(93.98,55.25) v1(93.98,53.34) v1(93.98,51.44) v1(93.98,49.53) v1(93.98,47.62) v1(93.98,45.72) v1(93.98,43.82) v1(93.98,41.91) v1(93.98,40.01) v1(93.98,38.1) v1(93.98,36.2) v1(93.98,34.29) v1(93.98,32.38) v1(93.98,30.48) v1(93.98,28.58) v1(93.98,26.67) v1(93.98,24.77) v1(93.98,22.86) v1(93.98,20.95) v1(93.98,19.05) v1(93.98,17.14) v1(93.98,15.24) v1(93.98,13.34) v1(93.98,11.43) v1(93.98,9.52) v1(93.98,7.62) v1(93.98,5.71) v1(93.98,3.81) v1(93.98,1.9) v2(45.94,48.25) v2(45.94,47.45) v2(45.94,46.65) v2(46.34,47.85) v2(46.34,47.05) v2(46.74,48.25) v2(46.74,47.45) v2(46.74,46.65) v2(47.14,47.85) v2(47.14,47.05) v2(47.14,46.25) v2(47.54,48.25) v2(47.54,47.45) v2(47.94,46.25) v2(48.34,45.85) v2(48.74,46.25) v2(49.14,48.25) v2(49.14,45.85)
INTVCC: length 68.6
  LAYER3 w0.203: 49.91,47.65 v1(51.5,49.24)
  LAYER3 w0.254: v1(55.93,17.79) 55.93,27.03 54.36,28.6 54.36,40.61 52.5,42.47 50.16,42.47 49.91,42.72 v1(49.91,45.47) 49.91,47.65 ; v1(51.5,49.24) 58.24,55.98 v1(62.87,55.98)
  BOTTOM w0.203: v1(49.91,45.47) 49.44,45 48.35,45 47.75,45.59 47.28,45.59 v2(46.74,45.05)
  BOTTOM w0.254: v1(51.5,49.24) 52.12,49.24 52.68,49.8 C7.2 ; JP1.5 v1(62.87,55.98) ; JP2.1 47.64,17.79 v1(55.93,17.79)
PG: length 59.9
  TOP w0.279: E7.1 v1(70.48,4.44)
  LAYER3 w0.254: v2(48.34,44.25) 48.34,43.45 49.99,41.8 v1(51.99,41.8) 53.73,40.06 53.73,28.46 55.3,26.9 55.3,12.32 55.93,11.68 55.93,11.19 56.27,10.85 56.77,10.85 57.33,10.29 69.34,10.29 70.48,9.14 v1(70.48,4.44)
  BOTTOM w0.254: v1(51.99,41.8) 52.92,41.8 R2.1
PGSET: length 13
  LAYER3 w0.254: v2(47.54,44.25) 47.54,43.45 50.46,40.53 v1(51.99,40.53) 53.17,39.35 53.17,37.43 v1(52.45,36.7)
  BOTTOM w0.203: v1(51.99,40.53) 52.92,40.53 R1.2
  BOTTOM w0.254: v1(52.45,36.7) 52.58,36.58 C25.2
PHMODE: length 53.2
  LAYER3 w0.203: 38.05,47.23 38.25,47.43 43.68,47.43 44.96,46.15 46.43,46.15 v2(47.54,45.05) ; JP2.2 v1(45.68,17.92)
  LAYER3 w0.254: 38.05,47.23 38.05,41.42 38.02,41.39 38.02,40.91 38.05,40.88 38.05,38.98 40.18,36.84 v1(40.18,17.92)
  BOTTOM w0.254: JP2.2 JP2.4 JP2.6 ; v1(45.68,17.92) v1(40.18,17.92)
RT: length 3.2
  TOP w0.254: R7.2 46.08,40.73 46.74,41.39 U1.D1
RUN: length 59.5
  TOP w0.203: v1(42.87,39.38) 43.32,39.83 43.41,39.83 43.74,40.15 43.74,40.25 44.22,40.73
  TOP w0.254: v1(38.84,45.61) 39.22,45.99 R5.1 ; U1.C1 45.94,42.96 44.32,41.35 R9.2
  TOP w0.279: 44.22,40.73 R9.2 ; E4.1 v1(52.7,4.57)
  LAYER3 w0.254: v1(38.61,41.15) 38.61,41.83 38.84,42.06 v1(38.84,45.61) ; v1(42.87,39.38) 42.87,11.35 49.66,4.57 v1(52.7,4.57)
  BOTTOM w0.254: v1(42.87,39.38) 42.28,39.97 40.04,39.97 39.74,39.67 39.25,39.67 38.61,40.32 v1(38.61,41.15)
SET: length 4.6
  TOP w0.203: C9.2 48.95,40.73 R3.2 47.37,41.35 47.54,41.52 U1.E1
SVN: length 8.4
  TOP w0.203: U1.A4 v2(43.75,45.85) ; C18.2 R4.1
  TOP w0.254: C18.2 38.82,47.76 v1(38.82,46.77)
  LAYER3 w0.203: v2(43.75,45.85) 43.03,45.85 42.76,46.11 39.48,46.11 v1(38.82,46.77)
SW: length 1.6
  BOTTOM w0.254: C8.2 48.39,48.08 48.42,48.05 48.42,47.53 v2(48.34,47.45)
SYNC: length 24.5
  TOP w0.254: v2(50.31,48.91) 50.31,48.62 U1.G6
  LAYER3 w0.254: v2(50.31,48.91) 50.31,49.18 57.98,56.85 63.48,56.85 JP1.6
  BOTTOM w0.254: JP1.6 JP1.4 JP1.2
TSENSE+: length 42.1
  TOP w0.254: v1(43.18,40.39) 43.18,41.02 45.14,42.98 U1.B1
  TOP w0.279: E14.1 41.91,4.75 v1(41.94,4.78)
  LAYER3 w0.254: v1(43.18,40.39) 42.71,40.39 41.73,39.41 41.73,7.92 41.94,7.72 v1(41.94,4.78)
TSENSE-: length 54.3
  TOP w0.279: E15.1 v1(27.89,4.78)
  LAYER3 w0.254: v1(27.89,4.78) 28.57,5.46 38.15,5.46 40.95,8.26 40.95,37.45 41.1,37.6 41.1,38.09 40.95,38.24 40.95,39.62 42.47,41.15 43.26,41.15 45.14,43.03 v2(45.14,44.25)
UNNAMED_6_CAP_I11_N1: length 1.6
  BOTTOM w0.254: C60.1 42.19,36.28 42.24,36.33 R12.2
UNNAMED_6_CAP_I138_N1: length 1.6
  BOTTOM w0.254: R8.2 C8.1
UNNAMED_6_CN6PJMPRSHRT_I48_S1: length 26.4
  TOP w0.254: E11.1 v1(85.09,57.79)
  LAYER3 w0.254: v1(85.09,57.79) 84.45,58.42 71.91,58.42 66.83,63.5 64.13,63.5 JP1.1
VOSNS: length 51.1
  TOP w0.203: R13.1 52.05,39.03 v1(52.05,39.03)
  TOP w0.254: U1.F1 48.34,41.96 48.9,41.4 49.96,41.4 50.15,41.21 50.15,39.37 50.49,39.03 R13.1 ; v1(85.09,29.21) E16.1
  LAYER3 w0.203: v1(85.09,29.21) 84.07,30.23 55.24,30.23 54.99,30.48 v1(54.99,37.72)
  BOTTOM w0.203: v1(54.99,37.72) 53.48,37.72 53.05,38.15 R11.1 52.21,38.87 v1(52.05,39.03)
VOUT: length 51.9
  TOP w0.203: v1(62.36,40.77) 62.36,40.64
  TOP w0.254: E3.1 90.11,41.09 90.88,41.09 91.67,41.87 C16.2 ; v1(64.15,19.29) J2.1 68.94,17.77 68.95,17.78 C24.2
  LAYER3 w0.254: v1(64.15,19.29) 64.15,23.76 68.71,28.32 85.47,28.32 85.85,28.7 E3.1
  BOTTOM w0.203: L2.2 61.25,41.66 v1(61.47,41.66)
  vias: v1(56.9,40.39) v1(57.53,40.64) v1(58.17,40.39) v1(58.8,40.64) v1(59.05,39.75) v1(59.05,38.99) v1(59.82,40.39) v1(60.71,40.39) v1(61.47,42.55) v1(61.47,40.77) v1(61.98,39.75) v1(61.98,38.86) v1(62.36,42.55) v1(62.36,41.66) v1(62.87,40.39) v1(63.63,40.39)

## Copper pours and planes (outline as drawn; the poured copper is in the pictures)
DGND_A on TOP, BOTTOM, LAYER2, LAYER3: 27.43,14.1 34.8,14.1 34.8,21.46 27.43,21.46
DGND_B on TOP, BOTTOM, LAYER2, LAYER3: 60.45,14.1 67.82,14.1 67.82,21.46 60.45,21.46
GND_SIGNAL on TOP, LAYER3: 45.21,37.08 46.61,37.08 46.61,39.75 45.21,39.75
VIN on TOP: 41.27,45.21 42.8,45.21 42.8,46.41 45.36,46.41 45.36,51.1 41.15,51.1 41.15,50.52 36.45,50.52 36.45,48.72 41.27,48.72
VIN on BOTTOM: 18.67,45.34 24.26,45.34 24.26,53.09 18.67,53.09
VIN on LAYER3: 18.54,53.09 37.59,53.09 37.59,51.7 45.47,51.7 45.47,46.36 44.07,46.36 44.07,48.12 29.34,48.12 29.34,34.67 15.75,34.67 12.45,31.37 8.38,31.37 5.59,34.16 5.59,42.29 18.54,42.29
DUTVOUT on TOP: 41.34,40.26 43.54,40.26 43.54,43.05 44.74,43.05 44.74,44.65 45.57,44.65 45.57,45.35 43.54,45.35 43.54,44.85 41.34,44.85
DUTVOUT on TOP: 53.47,46.99 64.01,46.99 64.01,45.22 60.96,45.22 60.96,42.55 56.39,42.55 56.39,44.07 54.99,44.07 54.99,40.26 48.9,40.26 48.9,44.64 47.9,44.64 47.9,45.33 53.47,45.33 ; 1 cut-out
DUTVOUT on BOTTOM: 42.14,45.85 55.14,45.85 55.14,43.07 51.74,43.07 51.74,41.45 42.8,41.45 42.8,40.39 41.53,40.39 41.53,44.45 42.14,44.45
DUTVOUT on BOTTOM: 56.39,43.32 63.25,43.32 63.25,46.62 56.39,46.62
GROUND on TOP: 1.27,80.01 94.61,80.01 94.61,1.27 1.27,1.27 ; 3 cut-outs
GROUND on TOP: 46.86,39.75 46.86,38.1 49.91,38.1 49.91,39.75
GROUND on BOTTOM: 1.27,1.27 94.61,1.27 94.61,80.01 1.27,80.01 ; 2 cut-outs
GROUND on LAYER2: 1.27,80.01 94.61,80.01 94.61,1.27 1.27,1.27 ; 2 cut-outs
GROUND on LAYER3: 1.27,80.01 94.61,80.01 94.61,1.27 1.27,1.27 ; 3 cut-outs
Net_2 on LAYER3 (solid shape): 47.24,38.35 46.38,38.35 46.38,39.62 47.24,39.62
Net_3 on TOP (solid shape): 5.33,44.7 3.81,44.7 3.81,45.85 5.33,45.85
Net_4 on TOP (solid shape): 92.46,44.45 90.93,44.45 90.93,45.47 92.46,45.47
UNNAMED_6_CAP_I100_N2 on BOTTOM: 21.72,61.85 24.77,61.85 24.77,54.86 21.72,54.86
VEMI on BOTTOM: 5.71,66.29 15.62,66.29 15.62,60.45 21.46,60.45 21.46,55.25 5.71,55.25
VOUT on TOP: 61.21,44.97 64.01,44.96 64.01,40.51 64.52,40.51 64.52,38.48 56.52,38.48 56.52,41.02 61.21,41.02
VOUT on BOTTOM: 54.36,38.37 63.12,38.37 63.12,42.56 54.36,42.56
VOUT on LAYER3: 56.53,42.56 78.74,42.56 78.74,42.55 90.68,42.55 90.68,31.88 56.53,31.88

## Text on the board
Ref Des/Silkscreen Bottom: 08-070348 | REV A | FOR ADI CUSTOMER USE ONLY
Ref Des/Silkscreen Top: SENSE | VIN | GND | 4V-16V | VEMI | TSENSE- | TSENSE+ | 180 PS | 120 PS | 90 PS | RUN | SYNC | FCM | PULSE | PG | 1V/12A | VOUT | CLKOUT | VO | EVAL-LTM4703-AZ | WITH LOW NOISE REFERENCE | 16V,12A uMODULE REGULATOR | LTM4703
User.15: PRIMARY SIDE (LAYER 1) | LAYER 3 | LAYER 2 | SECONDARY SIDE (LAYER 4) | SECONDARY SILKSCREEN | PRIMARY SILKSCREEN | PRIMARY SOLDER MASK | SECONDARY SOLDER MASK | INTENTIONAL SHORTS; | TEST REQUIREMENTS; | SPECIFICATIONS: | MATERIALS; | MATERIAL FAMILY; | CLADDING; | SOLDER MASK; | IC_U1; | SILK SCREEN; | SURFACE FINISH; | VIA HOLES; | PER IPC-4552 LATEST REVISION | 100% NETLIST ELECTRICAL VERIFICATION USING CUSTOMER | SUPPLIED IPC-D-356 NETLIST FOR OPENS AND SHORTS WHEN | "GERBER DATA" IS PROVIDED. THIS VERIFICATION ALSO | REQUIRED FOR "ODB++" DATA PER EMBEDDED NETLIST. | IF SUPPLIED DATA INCLUDES A FILE "READ_ME.2", THEN | INTENTIONAL NET SHORTS EXIST. CUSTOMER REVIEW AND APPROVAL | IS REQUIRED IF SUPPLIED DATA REPORTS ANY CONDITION THAT | DOES NOT MATCH "READ_ME.2" FILE PROVIDED. | ALL LAMINATES AND BONDING MATERIALS SHOULD BE SELECTED FROM | IPC-4101 OR IPC-4103, MINIMUM Tg>170degC, Td>300degC, | U.L. RATING OF 94 V-0 | FR406 | EXTERNAL LAYERS 1 OZ. COPPER, OVERPLATE TO 2 OZ. | INTERNAL LAYERS 2 OZ. COPPER. | SHALL BE LIQUID PHOTOIMAGEABLE (LPI) APPLIED ON BOTH SIDES | OVER BARE COPPER OR GOLD AND SHALL MEET IPC-SM-840 | (LATEST REV.) CLASS 3. COLOR GREEN. | CLADDING SPECIFICATIONS THEN THE LAYER STACKUP SHALL | TAKE PRECEDENCE. | DESIGN HAS SOLDER MASK DEFINED PADS ON U1. | U1 SOLDERMASK IS 16 MIL AND PAD SIZE IS 20 MIL. | DO NOT CHANGE PAD SIZE OR SOLDER MASK SIZE. | NOTE:IF THE LAYER STACKUP CONFLICTS WITH THE ABOVE | PLUG ALL VIA'S WITH CONDUCTIVE COPPER AND PLATE OVER. | PLANARIZE FINAL SURFACE. | ENIG (Electroless Nickel/Immersion Gold) | SHALL BE PERMANENT NON-CONDUCTIVE EPOXY INK, COLOR: WHITE | SYNTHETIC INKJET PRINTING ALLOWED FOR DENSE BOARDS, | COLOR: WHITE | REQUIREMENTS: | 1.    REFER TO IPC-6010 SERIES (LATEST REV.), CLASS 2 FOR | FABRICATION UNLESS OTHERWISE SPECIFIED. | 2.    ACCEPTABILITY PER ANALOG DEVICES, INC. SPECIFICATION TST00115, | (LATEST REVISION.) | 3.    MODIFICATIONS TO THE ARTWORK ARE NOT ALLOWED WITHOUT | WRITTEN AUTHORIZATION. | 4.    HOLE PATTERN TOLERANCES FOR UNDIMENSIONED HOLES SHALL BE | A DIAMETER OF 0.005 INCHES FROM THEIR TRUE POSITION. | 5.    PLATED HOLE WALL THICKNESS SHALL NOT BE LESS THAN 0.001 INCH | MINIMUM AVERAGE, WITH NO READING LESS THAN .0008 BY | CROSS SECTION. | 6.    HOLE DIAMETERS APPLY AFTER PLATING. | 7.    FINISHED CONDUCTOR WIDTHS SHALL NOT BE REDUCED FROM THE | NOMINAL INDICATED ON THE MASTER PATTERN, BY MORE THAN THE | CONDUCTOR THICKNESS. | 8.    MINIMUM DESIGN LINE WIDTH IS .006 INCH. | 9.    MINIMUM DESIGN SPACING IS .006 INCH. | 10.    NON-FUNCTIONAL PAD REMOVAL FROM INNER SIGNAL LAYERS MAY BE | PERFORMED AFTER CUSTOMER APPROVAL. | 11.    IF PAD SIZES PROVIDED ARE NOT LARGE ENOUGH TO MAINTAIN | ANNULAR RING REQUIREMENT, MFGR. MAY REQUEST APPROVAL TO | TEAR DROP PADS TO MAINTAIN ANNULAR RING. (AT PAD TO TRACE | INTERSECTION ONLY AND ELECTRICAL INTEGRITY MUST BE MAINTAINED.) | 12.    THIEVING MAY BE ADDED TO COMPENSATE FOR LOW COPPER DENSITY | AREAS ON THIS DESIGN ONLY AFTER REVIEW AND APPROVAL FROM | THE CUSTOMER: | A. THIEVING TO CARD EDGE, FIDUCIALS, NON-PLATED THROUGH HOLES, | ALL OTHER FEATURES TO BE 0.200 INCH MINIMUM. | B. THERE SHALL BE NO THIEVING IN ANY AREAS FREE OF SOLDER | MASK OR INTERNAL COPPER PLANES. | 13.    MFGR. TO LEGIBLY ETCH OR STAMP/SCREEN WITH PERMANENT | NON-CONDUCTIVE INK ON SECONDARY SIDE IN A CLEAR AREA | UNLESS OTHERWISE INDICATED; | A. U.L. CODE-FLAMMABILITY RATING   D. MFGR LOGO | B. DATE CODE (STAMP).              E. SUCCESSFUL ELECTRICAL TEST. | C. LOT NUMBER | 14.    REPAIRS PER IPC-7711/21 (LATEST REV.) ARE ALLOWED. | REPAIRS ARE NOT ALLOWED IN ANY AREA DEFINED ON GOLD_PRM AND/OR | GOLD_SEC ARTWORK LAYERS WHEN PROVIDED IN GERBER OR ODB++ DATA. | NOMINAL | FINISHED | THICKNESS | 0.062" +/-10% | 4 LAYER STACKUP
User.17: LAYER2
User.18: LAYER3 | 08-      -08
User.19: L4 SECONDARY | 08-      -02
User.45: FIGURE | SIZE | 7.0 | 12.0 | 40.0 | 213.0 | 187.0 | PLATED | NON-PLATED | FINISHED HOLES IN MILS | ALL UNITS ARE IN MILS | QTY | 35 | 565 | 12 | 5 | 4 | TOLERANCE/NOTES
